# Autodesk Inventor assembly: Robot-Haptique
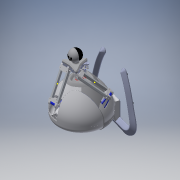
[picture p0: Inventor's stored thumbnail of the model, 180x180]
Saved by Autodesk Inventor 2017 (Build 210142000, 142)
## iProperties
Part Number: Robot-Haptique
Material: Générique
Document SubType Name: Assembly
Designer: Bruno
Author: Bruno
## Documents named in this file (7)
- D:\Cours\1-Cours-2018-19\1Ssi\7- EDC-mvt\Haptique-2017\Reel-Inventor\Robot-Haptique.iam
- D:\Cours\1-Cours-2018-19\1Ssi\7- EDC-mvt\Haptique-2017\Reel-Inventor\bati.iam
- D:\Cours\1-Cours-2018-19\1Ssi\7- EDC-mvt\Haptique-2017\Reel-Inventor\bras.iam
- D:\Cours\1-Cours-2018-19\1Ssi\7- EDC-mvt\Haptique-2017\Reel-Inventor\joint.iam
- D:\Cours\1-Cours-2018-19\1Ssi\7- EDC-mvt\Haptique-2017\Reel-Inventor\BIELLE PARALLELOGRAMME.iam
- D:\Cours\1-Cours-2018-19\1Ssi\7- EDC-mvt\Haptique-2017\Reel-Inventor\manette-finie.iam
- D:\Cours\1-Cours-2018-19\1Ssi\7- EDC-mvt\Haptique-2017\Reel-Inventor\ROTOR.iam
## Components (20 placed, 6 different names)
1. bati:1 [sub-assembly] — Logement:1, Logement:2, Logement:3, Placage:3, Placage:4, Placage:5, Placage:6, Placage:7, Placage:8
2. bras:1 [sub-assembly] — Logement:2, Logement:5
3. bras:2 [sub-assembly] — Logement:1, Logement:4
4. bras:3 [sub-assembly] — Logement:3, Logement:6
5. joint:1 [sub-assembly] — Logement:13, Placage:2, Logement:19
6. joint:2 [sub-assembly] — Logement:15, Logement:16, Logement:18
7. joint:3 [sub-assembly] — Logement:11, Placage:1, Logement:17
8. joint:4 [sub-assembly] — Logement:6, Logement:8, Logement:12
9. joint:5 [sub-assembly] — Logement:5, Logement:9, Logement:14
10. joint:6 [sub-assembly] — Logement:4, Logement:7, Logement:10
11. BIELLE PARALLELOGRAMME:1 [sub-assembly] — Logement:7, Placage:2
12. BIELLE PARALLELOGRAMME:2 [sub-assembly] — Logement:8, Placage:1
13. BIELLE PARALLELOGRAMME:3 [sub-assembly] — Logement:9, Logement:16
14. BIELLE PARALLELOGRAMME:4 [sub-assembly] — Logement:14, Logement:15
15. BIELLE PARALLELOGRAMME:5 [sub-assembly] — Logement:10, Logement:13
16. BIELLE PARALLELOGRAMME:6 [sub-assembly] — Logement:11, Logement:12
17. manette-finie:1 [sub-assembly] — Logement:17, Logement:18, Logement:19
18. ROTOR:1 [sub-assembly] — Placage:3, Placage:6
19. ROTOR:2 [sub-assembly] — Placage:5, Placage:8
20. ROTOR:3 [sub-assembly] — Placage:4, Placage:7
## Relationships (27: Insert 19, Mate 8)
- Logement:1 [Insert]: bati:1 ↔ bras:2
- Logement:2 [Insert]: bati:1 ↔ bras:1
- Logement:3 [Insert]: bati:1 ↔ bras:3
- Logement:4 [Insert]: bras:2 ↔ joint:6
- Logement:5 [Insert]: bras:1 ↔ joint:5
- Logement:6 [Insert]: bras:3 ↔ joint:4
- Logement:7 [Insert]: joint:6 ↔ BIELLE PARALLELOGRAMME:1
- Logement:8 [Insert]: joint:4 ↔ BIELLE PARALLELOGRAMME:2
- Logement:9 [Insert]: joint:5 ↔ BIELLE PARALLELOGRAMME:3
- Logement:10 [Insert]: joint:6 ↔ BIELLE PARALLELOGRAMME:5
- Logement:11 [Insert]: joint:3 ↔ BIELLE PARALLELOGRAMME:6
- Logement:12 [Insert]: joint:4 ↔ BIELLE PARALLELOGRAMME:6
- Placage:1 [Mate]: joint:3 ↔ BIELLE PARALLELOGRAMME:2
- Logement:13 [Insert]: joint:1 ↔ BIELLE PARALLELOGRAMME:5
- Placage:2 [Mate]: joint:1 ↔ BIELLE PARALLELOGRAMME:1
- Logement:14 [Insert]: joint:5 ↔ BIELLE PARALLELOGRAMME:4
- Logement:15 [Insert]: joint:2 ↔ BIELLE PARALLELOGRAMME:4
- Logement:16 [Insert]: joint:2 ↔ BIELLE PARALLELOGRAMME:3
- Logement:17 [Insert]: joint:3 ↔ manette-finie:1
- Logement:18 [Insert]: joint:2 ↔ manette-finie:1
- Logement:19 [Insert]: joint:1 ↔ manette-finie:1
- Placage:3 [Mate]: bati:1 ↔ ROTOR:1
- Placage:4 [Mate]: bati:1 ↔ ROTOR:3
- Placage:5 [Mate]: bati:1 ↔ ROTOR:2
- Placage:6 [Mate]: bati:1 ↔ ROTOR:1
- Placage:7 [Mate]: bati:1 ↔ ROTOR:3
- Placage:8 [Mate]: bati:1 ↔ ROTOR:2
